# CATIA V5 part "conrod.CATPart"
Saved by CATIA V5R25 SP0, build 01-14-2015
Part number: conrod
Bounding box of the stored display mesh (mm): x -2.5 to 2.5, y -12.499 to 12.499, z -12.496 to 87.496
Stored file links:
  C:\Users\feridun\Desktop\krank biyel\conrod.CATPart
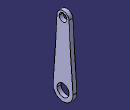
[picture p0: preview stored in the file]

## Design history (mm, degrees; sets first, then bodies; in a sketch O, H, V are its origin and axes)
Sketch1 on yz-plane, origin (0, 0, 0), H (0, 1, 0), V (0, 0, 1)
  arc A1 centre (0, 0) radius 12.5 from (-12.4756, 0.7813) to (12.4756, 0.7812) ccw
  arc A2 centre (0, 80) radius 7.5 from (7.4853, 80.4688) to (-7.4853, 80.4688) ccw
  point P1 (0, 80)
  reference intersected line E1 through (0, 0) direction (-1, 0) from xy-plane
  line L1 (12.4756, 0.7812) -> (7.4853, 80.4688)
  line L2 (-12.4756, 0.7812) -> (-7.4853, 80.4688)
  circle A3 centre (0, 80) radius 5
  circle A4 centre (0, 0) radius 7.5
  radius A1 = 12.5
  radius A2 = 7.5
  distance P1 E1 = 80
  radius A3 = 5
  radius A4 = 7.5
  coincidence: P1 V
  tangency: L1 A1, L1 A2, L2 A1, L2 A2
Pad1: profile Sketch1, direction (1, 0, 0), length 2.5, mirrored extent
Body1 (main body)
